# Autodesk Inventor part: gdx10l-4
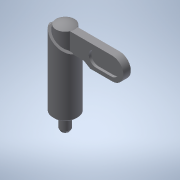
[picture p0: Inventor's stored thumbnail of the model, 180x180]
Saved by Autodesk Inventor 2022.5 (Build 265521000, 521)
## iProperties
Created: 2016-12
Part Number: gdx10l-4
Material: 一般
Document SubType Name: Modeling
Designer: imaocorp
Density: 1 g/cm^3
Appearance: 既定
Author: imaocorp
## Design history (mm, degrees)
node "gdx10l-4.x_t1"
node "gdx10l-4"
node "Base1"
